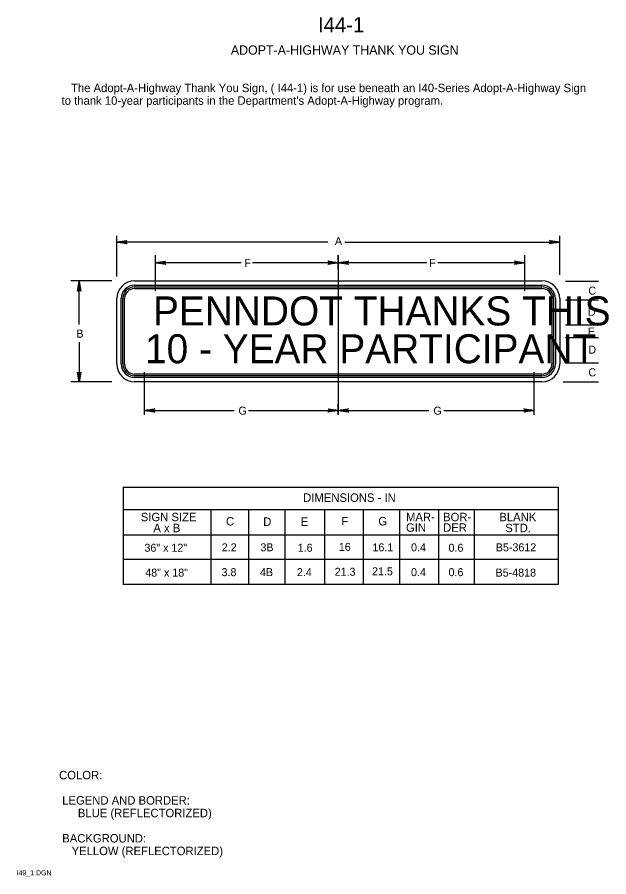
# Model space of a CAD drawing. Extents: x 0.013 to 0.188, y 0.004 to 0.259.
import ezdxf

# ---------------------------------------------------------------- set-up
doc = ezdxf.new("R2010")
doc.units = 0
for name, color, linetype in [('1', 7, 'Continuous'), ('2', 7, 'Continuous'), ('3', 7, 'Continuous')]:
    doc.layers.add(name, color=color, linetype=linetype)

# ---------------------------------------------------------------- blocks, each defined once
blk = doc.blocks.new('RARROW')
at = {"layer": '3'}
for p, q in [((-2.156, 0.285), (-2.2665, 0.384625)), ((-2.2665, 0.384625), (0, 0)), ((0, 0), (-2.2665, -0.379125)), ((-2.156, 0.285), (-2.075625, 0.12075)), ((0, 0), (-2.156, 0.285)), ((-2.14975, -0.2705), (0, 0)), ((-2.075625, 0.12075), (0, 0)), ((0, 0), (-2.074, -0.108)), ((-2.2665, -0.379125), (-2.14975, -0.2705)), ((-2.074, -0.108), (-2.14975, -0.2705))]:
    blk.add_line(p, q, dxfattribs=at)

msp = doc.modelspace()

# ---------------------------------------------------------------- linework, layer by layer
at = {"layer": '3'}
for p, q in [((0.04225, 0.18213), (0.04225, 0.19425)), ((0.17375, 0.18263), (0.17375, 0.19425)), ((0.10487, 0.19237), (0.04225, 0.19237)), ((0.11, 0.19237), (0.17375, 0.19237)), ((0.05375, 0.17788), (0.05375, 0.1885)), ((0.108, 0.18425), (0.108, 0.1885)), ((0.108, 0.1885), (0.108, 0.14113)), ((0.16337, 0.17788), (0.16337, 0.1885)), ((0.07913, 0.18625), (0.05375, 0.18625)), ((0.108, 0.18625), (0.08256, 0.18625)), ((0.13425, 0.18625), (0.108, 0.18625)), ((0.16337, 0.18625), (0.13754, 0.18625)), ((0.04075, 0.18088), (0.02863, 0.18088)), ((0.03112, 0.16787), (0.03112, 0.18088)), ((0.04755, 0.18088), (0.16845, 0.18088)), ((0.04755, 0.17957), (0.16845, 0.17957)), ((0.04755, 0.17907), (0.16845, 0.17907)), ((0.1755, 0.18075), (0.18525, 0.18075)), ((0.04755, 0.17857), (0.16845, 0.17857)), ((0.04225, 0.15618), (0.04225, 0.17557)), ((0.04355, 0.15618), (0.04355, 0.17557)), ((0.04405, 0.15618), (0.04405, 0.17557)), ((0.04455, 0.15618), (0.04455, 0.17557)), ((0.17145, 0.17557), (0.17145, 0.15618)), ((0.17195, 0.17557), (0.17195, 0.15618)), ((0.17245, 0.17557), (0.17245, 0.15618)), ((0.17375, 0.17557), (0.17375, 0.15618)), ((0.1755, 0.17525), (0.18525, 0.17525)), ((0.1755, 0.16775), (0.18525, 0.16775)), ((0.1755, 0.164), (0.18525, 0.164)), ((0.03112, 0.16262), (0.03112, 0.15088)), ((0.1755, 0.1565), (0.18525, 0.1565)), ((0.16845, 0.15318), (0.04755, 0.15318)), ((0.0505, 0.14113), (0.0505, 0.15375)), ((0.16612, 0.14113), (0.16612, 0.15375)), ((0.04075, 0.15088), (0.02863, 0.15088)), ((0.16845, 0.15268), (0.04755, 0.15268)), ((0.16845, 0.15218), (0.04755, 0.15218)), ((0.16845, 0.15088), (0.04755, 0.15088)), ((0.17475, 0.15088), (0.18525, 0.15088)), ((0.108, 0.14113), (0.108, 0.14425)), ((0.0505, 0.14238), (0.07712, 0.14238)), ((0.08137, 0.14238), (0.108, 0.14238)), ((0.108, 0.14238), (0.13487, 0.14238)), ((0.13933, 0.14238), (0.16612, 0.14238)), ((0.04412, 0.11963), (0.17325, 0.11963)), ((0.04412, 0.11963), (0.04412, 0.09075)), ((0.17325, 0.11963), (0.17325, 0.09075)), ((0.17325, 0.11288), (0.04412, 0.11288)), ((0.07022, 0.1129), (0.07022, 0.09075)), ((0.08138, 0.11275), (0.08138, 0.09075)), ((0.09212, 0.11275), (0.09212, 0.09075)), ((0.10388, 0.11275), (0.10388, 0.09075)), ((0.11538, 0.11275), (0.11538, 0.09075)), ((0.12615, 0.11275), (0.12615, 0.09075)), ((0.13772, 0.11275), (0.13772, 0.09075)), ((0.14836, 0.11275), (0.14836, 0.09075)), ((0.17325, 0.10537), (0.04412, 0.10537)), ((0.17325, 0.09813), (0.04412, 0.09813)), ((0.17325, 0.09075), (0.04412, 0.09075))]:
    msp.add_line(p, q, dxfattribs=at)
for centre, radius, start, end in [((0.04755, 0.17557), 0.0053, 90, 180), ((0.04755, 0.17557), 0.004, 90, 180), ((0.04755, 0.17557), 0.0035, 90, 180), ((0.16845, 0.17557), 0.0053, 0, 90), ((0.16845, 0.17557), 0.004, 0, 90), ((0.16845, 0.17557), 0.0035, 0, 90), ((0.04755, 0.17557), 0.003, 90, 180), ((0.16845, 0.17557), 0.003, 0, 90), ((0.04755, 0.15618), 0.0053, 180, 270), ((0.04755, 0.15618), 0.004, 180, 270), ((0.04755, 0.15618), 0.0035, 180, 270), ((0.04755, 0.15618), 0.003, 180, 270), ((0.16845, 0.15618), 0.0053, 270, 0), ((0.16845, 0.15618), 0.004, 270, 0), ((0.16845, 0.15618), 0.0035, 270, 0), ((0.16845, 0.15618), 0.003, 270, 0)]:
    msp.add_arc(centre, radius, start, end, dxfattribs=at)

# ---------------------------------------------------------------- block references
at = {"layer": '3', "xscale": 0.0013236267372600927, "yscale": 0.001309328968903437}
for p, rotation in [((0.04225, 0.19237), 180), ((0.05375, 0.18625), 180), ((0.108, 0.18625), 180), ((0.03112, 0.18075), 90), ((0.03112, 0.15075), -90), ((0.0505, 0.14238), 180), ((0.108, 0.14238), 180)]:
    msp.add_blockref('RARROW', p, dxfattribs=dict(at, rotation=rotation))
for p in [(0.17375, 0.19237), (0.108, 0.18625), (0.16337, 0.18625), (0.108, 0.14238), (0.16612, 0.14238)]:
    msp.add_blockref('RARROW', p, dxfattribs=at)

# ---------------------------------------------------------------- texts
at = {"layer": '1'}
for s, height, p in [('I44-1', 0.0045, (0.102, 0.25462)), ('ADOPT-A-HIGHWAY THANK YOU SIGN', 0.0027503, (0.07612, 0.248)), ('COLOR:', 0.0025, (0.02513, 0.03288)), (' LEGEND AND BORDER:', 0.0024998, (0.02513, 0.02538)), ('      BLUE (REFLECTORIZED)', 0.0024998, (0.02513, 0.02163)), (' BACKGROUND:', 0.0024998, (0.02513, 0.01413)), ('    YELLOW (REFLECTORIZED)', 0.0024998, (0.02513, 0.01038)), ('I49_1.DGN', 0.0015, (0.0125, 0.00438))]:
    msp.add_text(s, height=height, dxfattribs=at).set_placement(p)
at = {"layer": '2'}
for s, height, p in [('   The Adopt-A-Highway Thank You Sign, ( I44-1) is for use beneath an I40-Series Adopt-A-Highway Sign', 0.00249975, (0.02588, 0.23688)), ("to thank 10-year participants in the Department's Adopt-A-Highway program.", 0.0024998, (0.02588, 0.23312))]:
    msp.add_text(s, height=height, dxfattribs=at).set_placement(p)
at = {"layer": '3'}
for s, height, p in [('A', 0.00238, (0.107, 0.1915)), ('F', 0.00238, (0.08013, 0.185)), ('F', 0.00238, (0.135, 0.185)), ('C', 0.00238, (0.18225, 0.17675)), ('PENNDOT THANKS THIS', 0.008625, (0.053, 0.16762)), ('D', 0.00238, (0.18213, 0.1705)), ('B', 0.00238, (0.03025, 0.164)), ('E', 0.00238, (0.18213, 0.16462)), ('10 - YEAR PARTICIPANT', 0.008625, (0.05063, 0.15638)), ('D', 0.00238, (0.18225, 0.15925)), ('C', 0.00238, (0.18225, 0.1525)), ('G', 0.00238, (0.07838, 0.14113)), ('G', 0.00238, (0.13625, 0.14113)), ('DIMENSIONS - IN', 0.0024998, (0.09758, 0.11525)), ('SIGN SIZE', 0.0025, (0.04938, 0.1095)), ('C', 0.0025, (0.07468, 0.10824)), ('D', 0.0025, (0.08573, 0.10812)), ('E', 0.0025, (0.09688, 0.10812)), ('F', 0.0025, (0.1089, 0.10825)), ('G', 0.0025, (0.11991, 0.10825)), ('MAR-', 0.0025, (0.12812, 0.1095)), ('BOR-', 0.0025, (0.13912, 0.1095)), ('BLANK', 0.0025, (0.15583, 0.1095)), ('A x B', 0.0025, (0.05312, 0.10625)), ('GIN', 0.0025, (0.12812, 0.10637)), ('DER', 0.0025, (0.13912, 0.10637)), ('STD.', 0.0025, (0.15758, 0.10625)), ('36" x 12"', 0.002375, (0.05046, 0.10044)), ('2.2', 0.002375, (0.07342, 0.10056)), ('3B', 0.002375, (0.08489, 0.10056)), ('1.6', 0.002375, (0.09596, 0.10044)), ('16', 0.002375, (0.10818, 0.10069)), ('16.1', 0.002375, (0.11815, 0.10056)), ('0.4', 0.002375, (0.12961, 0.10056)), ('0.6', 0.002375, (0.14074, 0.10044)), ('B5-3612', 0.002375, (0.15477, 0.10056)), ('48" x 18"', 0.002375, (0.05071, 0.09306)), ('3.8', 0.002375, (0.07336, 0.09319)), ('4B', 0.002375, (0.08477, 0.09319)), ('2.4', 0.002375, (0.09573, 0.09319)), ('21.3', 0.002375, (0.10693, 0.09331)), ('21.5', 0.002375, (0.11803, 0.09344)), ('0.4', 0.002375, (0.12961, 0.09319)), ('0.6', 0.002375, (0.14074, 0.09319)), ('B5-4818', 0.002375, (0.15471, 0.09306))]:
    msp.add_text(s, height=height, dxfattribs=at).set_placement(p)

doc.saveas('drawing.dxf')
